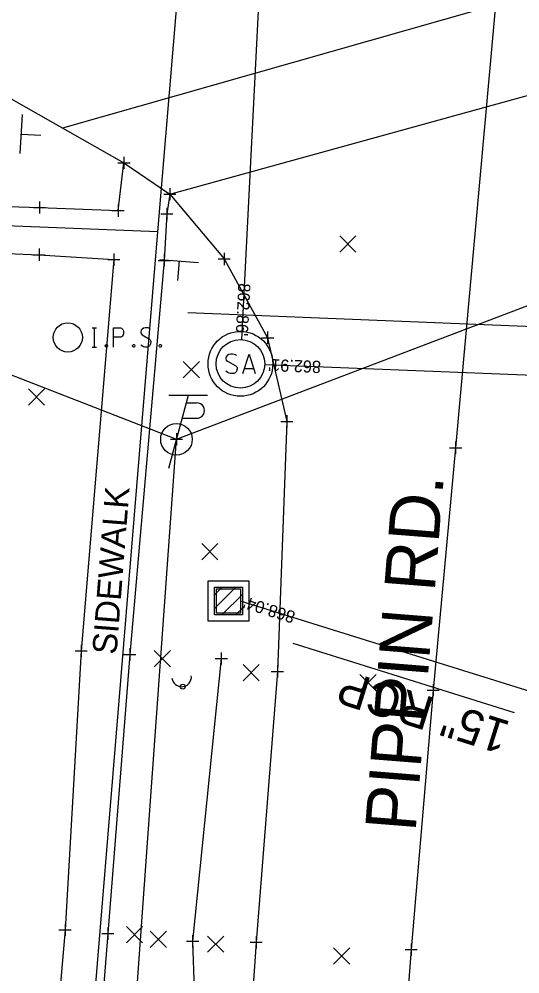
# Model space of a CAD drawing. Extents: x 1380440 to 1381945, y 468756 to 470369.
# Drawn here: x 1381582.8 to 1381624.1, y 470176.8 to 470255.4 of the extents above; entities that cross this region are included whole.
import ezdxf

# ---------------------------------------------------------------- set-up
doc = ezdxf.new("R2010")
doc.units = 0
for name, color, linetype in [('DR_P_Headwall', 7, 'Continuous'), ('GE_P_Driveway_CL', 7, 'Continuous'), ('PM_X_CL_Double_Solid', 7, 'Continuous'), ('PM_X_Crosswalk', 7, 'Continuous'), ('PV_P_Curb', 7, 'Continuous'), ('PV_P_Curb_Ramp', 7, 'Continuous'), ('PV_P_Drive', 7, 'Continuous'), ('PV_P_EOP', 7, 'Continuous'), ('PV_P_Joint', 7, 'Continuous'), ('PV_P_Walk', 7, 'Continuous'), ('PV_X_COP', 7, 'Continuous'), ('RW_P_Esmt_TMP', 7, 'Continuous'), ('RW_X_CL', 7, 'Continuous'), ('SC_Scratch1', 7, 'Continuous'), ('SC_Shading1', 7, 'Continuous'), ('SH_Named_Boundary', 7, 'Continuous'), ('UT_X_Gas', 7, 'Continuous'), ('UT_X_Overhead_Combined', 7, 'Continuous'), ('UT_X_Sanitary_Line', 7, 'Continuous'), ('X-CL', 7, 'Continuous'), ('X-SUBDIVISION', 7, 'Continuous')]:
    doc.layers.add(name, color=color, linetype=linetype)

msp = doc.modelspace()

# ---------------------------------------------------------------- linework, layer by layer
at = {"layer": 'DR_P_Headwall'}
for points in [[(1381542.819, 470241.667), (1381568.313, 470240.569), (1381578.584, 470240.095), (1381584.519, 470239.902), (1381590.984, 470239.649), (1381591.472, 470243.585)], [(1381595.246, 470241.001), (1381595.008, 470239.378), (1381594.794, 470235.558), (1381591.944, 470203.127), (1381590.146, 470180.146), (1381585.845, 470126.107), (1381581.453, 470072.835), (1381577.219, 470021.474), (1381573.16, 469971.68), (1381569.701, 469929.431), (1381565.599, 469880.892), (1381564.412, 469866.997), (1381562.952, 469848.389), (1381561.899, 469840.883)], [(1381542.564, 470237.64), (1381568.337, 470236.695), (1381578.506, 470236.262), (1381584.487, 470236.02), (1381590.642, 470235.62), (1381587.955, 470203.415), (1381586.625, 470180.461), (1381581.932, 470126.464), (1381577.652, 470073.239), (1381573.197, 470021.541), (1381569.148, 469971.738), (1381565.643, 469929.65), (1381561.644, 469881.156), (1381560.457, 469867.318), (1381559.272, 469848.708), (1381558.347, 469840.136)]]:
    msp.add_lwpolyline(points, dxfattribs=at)
at = {"layer": 'GE_P_Driveway_CL'}
for p, q in [((1381609.232, 470236.233), (1381610.566, 470237.568)), ((1381609.232, 470237.568), (1381610.566, 470236.233)), ((1381596.356, 470225.899), (1381597.69, 470227.234)), ((1381596.356, 470227.234), (1381597.69, 470225.899)), ((1381583.61, 470223.635), (1381584.944, 470224.97)), ((1381583.61, 470224.97), (1381584.944, 470223.635)), ((1381597.872, 470210.912), (1381599.206, 470212.247)), ((1381597.872, 470212.247), (1381599.206, 470210.912)), ((1381593.972, 470202.11), (1381595.306, 470203.445)), ((1381593.972, 470203.445), (1381595.306, 470202.11)), ((1381601.274, 470200.95), (1381602.608, 470202.285)), ((1381601.274, 470202.285), (1381602.608, 470200.95)), ((1381610.886, 470200.127), (1381612.22, 470201.462)), ((1381610.886, 470201.462), (1381612.22, 470200.127)), ((1381591.673, 470179.39), (1381593.007, 470180.725)), ((1381591.673, 470180.725), (1381593.007, 470179.39)), ((1381593.643, 470178.999), (1381594.977, 470180.334)), ((1381593.643, 470180.334), (1381594.977, 470178.999)), ((1381598.361, 470178.605), (1381599.695, 470179.94)), ((1381598.361, 470179.94), (1381599.695, 470178.605)), ((1381608.724, 470177.633), (1381610.058, 470178.968)), ((1381608.724, 470178.968), (1381610.058, 470177.633))]:
    msp.add_line(p, q, dxfattribs=at)
at = {"layer": 'PM_X_CL_Double_Solid'}
msp.add_lwpolyline([(1381618.765, 470220.138), (1381616.919, 470200.188), (1381615.103, 470178.831), (1381610.946, 470124.776), (1381606.492, 470071.232), (1381602.26, 470019.361), (1381598.177, 469969.796), (1381595.011, 469928.064), (1381590.91, 469878.811), (1381589.36, 469859.114), (1381585.986, 469815.579), (1381581.288, 469760.779), (1381580.3, 469747.86), (1381578.724, 469729.445), (1381576.782, 469708.953), (1381575.288, 469689.792), (1381572.756, 469657.561), (1381569.364, 469615.703), (1381565.36, 469567.235), (1381561.161, 469537.516), (1381558.939, 469486.814), (1381555.385, 469442.034), (1381550.974, 469391.016)], dxfattribs=at)
at = {"layer": 'PM_X_Crosswalk'}
for p, q in [((1381638.406, 470261.247), (1381586.418, 470246.45)), ((1381595.246, 470241.001), (1381641.186, 470253.713))]:
    msp.add_line(p, q, dxfattribs=at)
at = {"layer": 'PV_P_Curb'}
msp.add_lwpolyline([(1381599.486, 470202.784), (1381597.124, 470179.514), (1381597.246, 470175.525), (1381597.199, 470175.029), (1381592.574, 470125.524), (1381589.105, 470072.434), (1381585.647, 470022.009), (1381581.714, 469971.399), (1381577.659, 469928.753), (1381573.101, 469880.444), (1381570.638, 469867.29)], dxfattribs=at)
at = {"layer": 'PV_P_Curb_Ramp'}
for p, q in [((1381601.057, 470229.041), (1381601.057, 470229.041)), ((1381601.057, 470227.041), (1381601.057, 470227.041)), ((1381601.057, 470227.041), (1381601.057, 470227.041)), ((1381601.057, 470227.041), (1381601.057, 470227.041)), ((1381601.057, 470225.041), (1381601.057, 470225.041)), ((1381600.076, 470209.187), (1381600.076, 470209.187)), ((1381600.076, 470208.52), (1381600.076, 470208.52)), ((1381599.076, 470207.52), (1381599.076, 470207.52)), ((1381600.076, 470207.52), (1381600.076, 470207.52)), ((1381600.076, 470207.52), (1381600.076, 470207.52)), ((1381600.076, 470207.52), (1381600.076, 470207.52)), ((1381601.076, 470207.52), (1381601.076, 470207.52)), ((1381600.076, 470206.52), (1381600.076, 470206.52)), ((1381600.076, 470205.854), (1381600.076, 470205.854))]:
    msp.add_line(p, q, dxfattribs=at)
msp.add_circle((1381601.057, 470227.041), 2, dxfattribs=at)
at = {"layer": 'PV_P_Drive'}
for p, q in [((1381582.936, 470244.359), (1381583.13, 470247.553)), ((1381583.033, 470245.956), (1381584.63, 470245.86)), ((1381594.413, 470235.634), (1381597.603, 470235.378)), ((1381596.008, 470235.506), (1381595.88, 470233.911))]:
    msp.add_line(p, q, dxfattribs=at)
at = {"layer": 'PV_P_EOP'}
for points in [[(1381600.724, 470227.727), (1381600.699, 470227.753), (1381600.661, 470227.778), (1381600.548, 470227.816), (1381600.409, 470227.841), (1381600.309, 470227.841), (1381600.271, 470227.841), (1381600.107, 470227.803), (1381599.969, 470227.727), (1381599.88, 470227.627), (1381599.855, 470227.526), (1381599.855, 470227.45), (1381599.88, 470227.349), (1381599.981, 470227.261), (1381600.674, 470226.883), (1381600.737, 470226.833), (1381600.762, 470226.783), (1381600.787, 470226.707), (1381600.787, 470226.631), (1381600.775, 470226.556), (1381600.762, 470226.505), (1381600.737, 470226.442), (1381600.712, 470226.392), (1381600.687, 470226.354), (1381600.649, 470226.316), (1381600.611, 470226.291), (1381600.561, 470226.266), (1381600.523, 470226.253), (1381600.409, 470226.241), (1381600.233, 470226.241), (1381600.12, 470226.266), (1381599.956, 470226.354), (1381599.855, 470226.43)], [(1381601.266, 470226.241), (1381601.77, 470227.841), (1381602.261, 470226.241)], [(1381602.135, 470226.619), (1381601.392, 470226.619)]]:
    msp.add_lwpolyline(points, dxfattribs=at)
for radius in [2.667, 2]:
    msp.add_circle((1381601.057, 470227.041), radius, dxfattribs=at)
at = {"layer": 'PV_P_Joint'}
for p, q in [((1381598.93, 470206.907), (1381600.689, 470208.666)), ((1381598.93, 470208.038), (1381599.558, 470208.666)), ((1381599.529, 470206.374), (1381601.222, 470208.067)), ((1381600.66, 470206.374), (1381601.222, 470206.936))]:
    msp.add_line(p, q, dxfattribs=at)
for points in [[(1381598.409, 470209.187), (1381601.743, 470209.187), (1381601.743, 470205.854), (1381598.409, 470205.854)], [(1381598.93, 470208.666), (1381601.222, 470208.666), (1381601.222, 470206.374), (1381598.93, 470206.374)], [(1381599.076, 470208.52), (1381601.076, 470208.52), (1381601.076, 470206.52), (1381599.076, 470206.52)]]:
    msp.add_lwpolyline(points, close=True, dxfattribs=at)
at = {"layer": 'PV_P_Walk'}
for points in [[(1381588.87, 470230.016), (1381589.223, 470230.016)], [(1381589.046, 470228.416), (1381589.046, 470230.016)], [(1381590.612, 470228.416), (1381590.612, 470230.016), (1381591.141, 470230.016), (1381591.196, 470230.003), (1381591.273, 470229.978), (1381591.306, 470229.953), (1381591.339, 470229.928), (1381591.383, 470229.865), (1381591.416, 470229.802), (1381591.438, 470229.701), (1381591.438, 470229.55), (1381591.427, 470229.499), (1381591.405, 470229.424), (1381591.361, 470229.336), (1381591.317, 470229.298), (1381591.284, 470229.273), (1381591.229, 470229.247), (1381591.141, 470229.235), (1381590.612, 470229.235)], [(1381593.621, 470229.902), (1381593.599, 470229.928), (1381593.566, 470229.953), (1381593.467, 470229.991), (1381593.345, 470230.016), (1381593.257, 470230.016), (1381593.224, 470230.016), (1381593.081, 470229.978), (1381592.96, 470229.902), (1381592.882, 470229.802), (1381592.86, 470229.701), (1381592.86, 470229.625), (1381592.882, 470229.524), (1381592.971, 470229.436), (1381593.577, 470229.058), (1381593.632, 470229.008), (1381593.654, 470228.958), (1381593.676, 470228.882), (1381593.676, 470228.806), (1381593.665, 470228.731), (1381593.654, 470228.681), (1381593.632, 470228.617), (1381593.61, 470228.567), (1381593.588, 470228.529), (1381593.555, 470228.491), (1381593.522, 470228.466), (1381593.478, 470228.441), (1381593.445, 470228.429), (1381593.345, 470228.416), (1381593.191, 470228.416), (1381593.092, 470228.441), (1381592.948, 470228.529), (1381592.86, 470228.605)], [(1381588.87, 470228.416), (1381589.223, 470228.416)], [(1381590.005, 470228.63), (1381590.06, 470228.63), (1381590.094, 470228.605), (1381590.127, 470228.555), (1381590.127, 470228.491), (1381590.094, 470228.441), (1381590.06, 470228.416), (1381590.005, 470228.416), (1381589.972, 470228.441), (1381589.939, 470228.491), (1381589.939, 470228.555), (1381589.972, 470228.605), (1381590.005, 470228.63)], [(1381592.254, 470228.63), (1381592.309, 470228.63), (1381592.342, 470228.605), (1381592.375, 470228.555), (1381592.375, 470228.491), (1381592.342, 470228.441), (1381592.309, 470228.416), (1381592.254, 470228.416), (1381592.221, 470228.441), (1381592.188, 470228.491), (1381592.188, 470228.555), (1381592.221, 470228.605), (1381592.254, 470228.63)], [(1381594.437, 470228.63), (1381594.492, 470228.63), (1381594.525, 470228.605), (1381594.558, 470228.555), (1381594.558, 470228.491), (1381594.525, 470228.441), (1381594.492, 470228.416), (1381594.437, 470228.416), (1381594.403, 470228.441), (1381594.371, 470228.491), (1381594.371, 470228.555), (1381594.403, 470228.605), (1381594.437, 470228.63)]]:
    msp.add_lwpolyline(points, dxfattribs=at)
msp.add_circle((1381586.851, 470229.214), 1.2, dxfattribs=at)
at = {"layer": 'PV_X_COP'}
for p, q in [((1381596.758, 470224.433), (1381595.152, 470218.433)), ((1381598.358, 470224.433), (1381595.158, 470224.433)), ((1381596.598, 470223.833), (1381597.448, 470223.833)), ((1381596.257, 470222.558), (1381597.448, 470222.558))]:
    msp.add_line(p, q, dxfattribs=at)
for centre, radius in [((1381595.795, 470220.833), 1.3), ((1381596.312, 470200.471), 0.2)]:
    msp.add_circle(centre, radius, dxfattribs=at)
for centre, radius, start, end in [((1381597.461, 470223.196), 0.638, 268.8767, 91.1233), ((1381596.221, 470201.266), 0.8, 186.5352, 6.5352)]:
    msp.add_arc(centre, radius, start, end, dxfattribs=at)
at = {"layer": 'RW_P_Esmt_TMP'}
msp.add_lwpolyline([(1381575.388, 470244.04), (1381576.993, 470244.172), (1381579.545, 470245.54), (1381580.634, 470247.96), (1381580.965, 470249.541), (1381591.472, 470243.585), (1381595.246, 470241.001), (1381599.724, 470235.672), (1381603.295, 470229.192), (1381604.877, 470222.306), (1381604.1, 470201.731), (1381602.36, 470179.429), (1381598.627, 470125.511), (1381593.594, 470071.886), (1381589.534, 470020.646), (1381585.494, 469971.089), (1381582.039, 469928.84), (1381578.382, 469880.278), (1381576.859, 469862.024), (1381576.832, 469860.709), (1381576.155, 469857.385), (1381571.588, 469847.123), (1381563.138, 469838.251)], dxfattribs=at)
at = {"layer": 'RW_X_CL'}
msp.add_line((1381605.369, 470204.055), (1381623.583, 470198.353), dxfattribs=at)
at = {"layer": 'SC_Shading1'}
msp.add_lwpolyline([(1381627.408, 470324.235), (1381625.025, 470294.425), (1381622.344, 470259.947), (1381618.765, 470220.138), (1381616.919, 470200.188), (1381615.103, 470178.831), (1381610.946, 470124.776), (1381606.492, 470071.232), (1381602.26, 470019.361), (1381598.177, 469969.796), (1381595.011, 469928.064), (1381590.91, 469878.811), (1381589.36, 469859.114), (1381585.986, 469815.579)], dxfattribs=at)
at = {"layer": 'SH_Named_Boundary'}
for p, q in [((1381591.472, 470244.085), (1381591.472, 470243.085)), ((1381591.472, 470244.085), (1381591.472, 470243.085)), ((1381590.972, 470243.585), (1381591.972, 470243.585)), ((1381590.972, 470243.585), (1381591.972, 470243.585)), ((1381591.472, 470243.585), (1381591.472, 470243.585)), ((1381591.472, 470243.585), (1381591.472, 470243.585)), ((1381594.746, 470241.001), (1381595.746, 470241.001)), ((1381594.746, 470241.001), (1381595.746, 470241.001)), ((1381594.746, 470241.001), (1381595.746, 470241.001)), ((1381595.246, 470241.501), (1381595.246, 470240.501)), ((1381595.246, 470241.501), (1381595.246, 470240.501)), ((1381595.246, 470241.501), (1381595.246, 470240.501)), ((1381595.246, 470241.001), (1381595.246, 470241.001)), ((1381595.246, 470241.001), (1381595.246, 470241.001)), ((1381595.246, 470241.001), (1381595.246, 470241.001)), ((1381584.519, 470240.402), (1381584.519, 470239.402)), ((1381590.984, 470240.149), (1381590.984, 470239.149)), ((1381584.019, 470239.902), (1381585.019, 470239.902)), ((1381584.519, 470239.902), (1381584.519, 470239.902)), ((1381590.484, 470239.649), (1381591.484, 470239.649)), ((1381590.984, 470239.649), (1381590.984, 470239.649)), ((1381594.508, 470239.378), (1381595.508, 470239.378)), ((1381595.008, 470239.878), (1381595.008, 470238.878)), ((1381595.008, 470239.378), (1381595.008, 470239.378)), ((1381584.487, 470236.52), (1381584.487, 470235.52)), ((1381583.987, 470236.02), (1381584.987, 470236.02)), ((1381584.487, 470236.02), (1381584.487, 470236.02)), ((1381590.142, 470235.62), (1381591.142, 470235.62)), ((1381590.642, 470236.12), (1381590.642, 470235.12)), ((1381590.642, 470235.62), (1381590.642, 470235.62)), ((1381594.294, 470235.558), (1381595.294, 470235.558)), ((1381594.794, 470236.058), (1381594.794, 470235.058)), ((1381594.794, 470235.558), (1381594.794, 470235.558)), ((1381599.224, 470235.672), (1381600.224, 470235.672)), ((1381599.724, 470236.172), (1381599.724, 470235.172)), ((1381599.724, 470235.672), (1381599.724, 470235.672)), ((1381602.795, 470229.192), (1381603.795, 470229.192)), ((1381603.295, 470229.692), (1381603.295, 470228.692)), ((1381603.295, 470229.192), (1381603.295, 470229.192)), ((1381604.377, 470222.306), (1381605.377, 470222.306)), ((1381604.877, 470222.806), (1381604.877, 470221.806)), ((1381604.877, 470222.306), (1381604.877, 470222.306)), ((1381595.795, 470221.333), (1381595.795, 470220.333)), ((1381595.795, 470221.333), (1381595.795, 470220.333)), ((1381595.795, 470221.333), (1381595.795, 470220.333)), ((1381595.795, 470221.333), (1381595.795, 470220.333)), ((1381595.295, 470220.833), (1381596.295, 470220.833)), ((1381595.295, 470220.833), (1381596.295, 470220.833)), ((1381595.295, 470220.833), (1381596.295, 470220.833)), ((1381595.295, 470220.833), (1381596.295, 470220.833)), ((1381595.795, 470220.833), (1381595.795, 470220.833)), ((1381595.795, 470220.833), (1381595.795, 470220.833)), ((1381595.795, 470220.833), (1381595.795, 470220.833)), ((1381595.795, 470220.833), (1381595.795, 470220.833)), ((1381618.765, 470220.638), (1381618.765, 470219.638)), ((1381618.265, 470220.138), (1381619.265, 470220.138)), ((1381618.765, 470220.138), (1381618.765, 470220.138)), ((1381587.455, 470203.415), (1381588.455, 470203.415)), ((1381587.955, 470203.915), (1381587.955, 470202.915)), ((1381587.955, 470203.415), (1381587.955, 470203.415)), ((1381591.944, 470203.627), (1381591.944, 470202.627)), ((1381599.486, 470203.284), (1381599.486, 470202.284)), ((1381591.444, 470203.127), (1381592.444, 470203.127)), ((1381591.944, 470203.127), (1381591.944, 470203.127)), ((1381598.986, 470202.784), (1381599.986, 470202.784)), ((1381599.486, 470202.784), (1381599.486, 470202.784)), ((1381603.6, 470201.731), (1381604.6, 470201.731)), ((1381604.1, 470202.231), (1381604.1, 470201.231)), ((1381604.1, 470201.731), (1381604.1, 470201.731)), ((1381616.419, 470200.188), (1381617.419, 470200.188)), ((1381616.919, 470200.688), (1381616.919, 470199.688)), ((1381616.919, 470200.188), (1381616.919, 470200.188)), ((1381586.125, 470180.461), (1381587.125, 470180.461)), ((1381586.625, 470180.961), (1381586.625, 470179.961)), ((1381586.625, 470180.461), (1381586.625, 470180.461)), ((1381590.146, 470180.646), (1381590.146, 470179.646)), ((1381589.646, 470180.146), (1381590.646, 470180.146)), ((1381590.146, 470180.146), (1381590.146, 470180.146)), ((1381597.124, 470180.014), (1381597.124, 470179.014)), ((1381602.36, 470179.929), (1381602.36, 470178.929)), ((1381596.624, 470179.514), (1381597.624, 470179.514)), ((1381597.124, 470179.514), (1381597.124, 470179.514)), ((1381601.86, 470179.429), (1381602.86, 470179.429)), ((1381602.36, 470179.429), (1381602.36, 470179.429)), ((1381614.603, 470178.831), (1381615.603, 470178.831)), ((1381615.103, 470179.331), (1381615.103, 470178.331)), ((1381615.103, 470178.831), (1381615.103, 470178.831))]:
    msp.add_line(p, q, dxfattribs=at)
at = {"layer": 'UT_X_Gas'}
for p, q in [((1381594.271, 470237.893), (1381601.452, 470324.794)), ((1381720.282, 470226.259), (1381596.732, 470231.245))]:
    msp.add_line(p, q, dxfattribs=at)
msp.add_lwpolyline([(1381485.898, 468926.411), (1381594.271, 470237.893), (1380558.001, 470279.291)], dxfattribs=at)
at = {"layer": 'UT_X_Overhead_Combined'}
for points in [[(1381540.8, 469054.263), (1381515.279, 469203.101), (1381529.165, 469390.12), (1381543.86, 469565.781), (1381559.775, 469757.408), (1381571.968, 469887.64), (1381581.264, 470018.199), (1381595.795, 470220.833), (1381665.562, 470247.404)], [(1381540.532, 470242.354), (1381595.795, 470220.833)]]:
    msp.add_lwpolyline(points, dxfattribs=at)
at = {"layer": 'UT_X_Sanitary_Line'}
for p, q in [((1381607.902, 470363.885), (1381601.157, 470229.038)), ((1381906.161, 470214.727), (1381603.055, 470226.96))]:
    msp.add_line(p, q, dxfattribs=at)
at = {"layer": 'X-CL'}
msp.add_line((1381632.903, 470197.558), (1381601.076, 470207.52), dxfattribs=at)

# ---------------------------------------------------------------- texts
at = {"layer": 'RW_X_CL'}
msp.add_text('15" RCP', height=2.8, rotation=162.61865, dxfattribs=at).set_placement((1381623.394, 470197.549))
at = {"layer": 'SC_Scratch1'}
for s, rotation, p in [("862.86'", 267.1364, (1381600.889, 470233.69)), ("862.91'", 177.68886, (1381607.704, 470227.273)), ("868.04'", 162.61865, (1381605.646, 470206.613))]:
    msp.add_text(s, height=1, rotation=rotation, dxfattribs=at).set_placement(p)
at = {"layer": 'X-SUBDIVISION'}
for s, height, rotation, p in [('PIPPIN RD.', 4.1667, 85.44278, (1381615.464, 470188.469)), ('SIDEWALK', 2, 85.52099, (1381590.858, 470203.069))]:
    msp.add_text(s, height=height, rotation=rotation, dxfattribs=at).set_placement(p)

doc.saveas('drawing.dxf')
